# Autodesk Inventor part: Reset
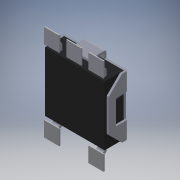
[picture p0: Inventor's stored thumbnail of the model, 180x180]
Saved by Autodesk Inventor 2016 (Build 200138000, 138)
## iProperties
Created: 2018-03
Part Number: Reset
Material: Générique
Document SubType Name: Modeling
Designer: Bruno
Density: 1 g/cm^3
Appearance: Par défaut
Author: Bruno
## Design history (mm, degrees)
feature "Composite1"
body "Srf1"
